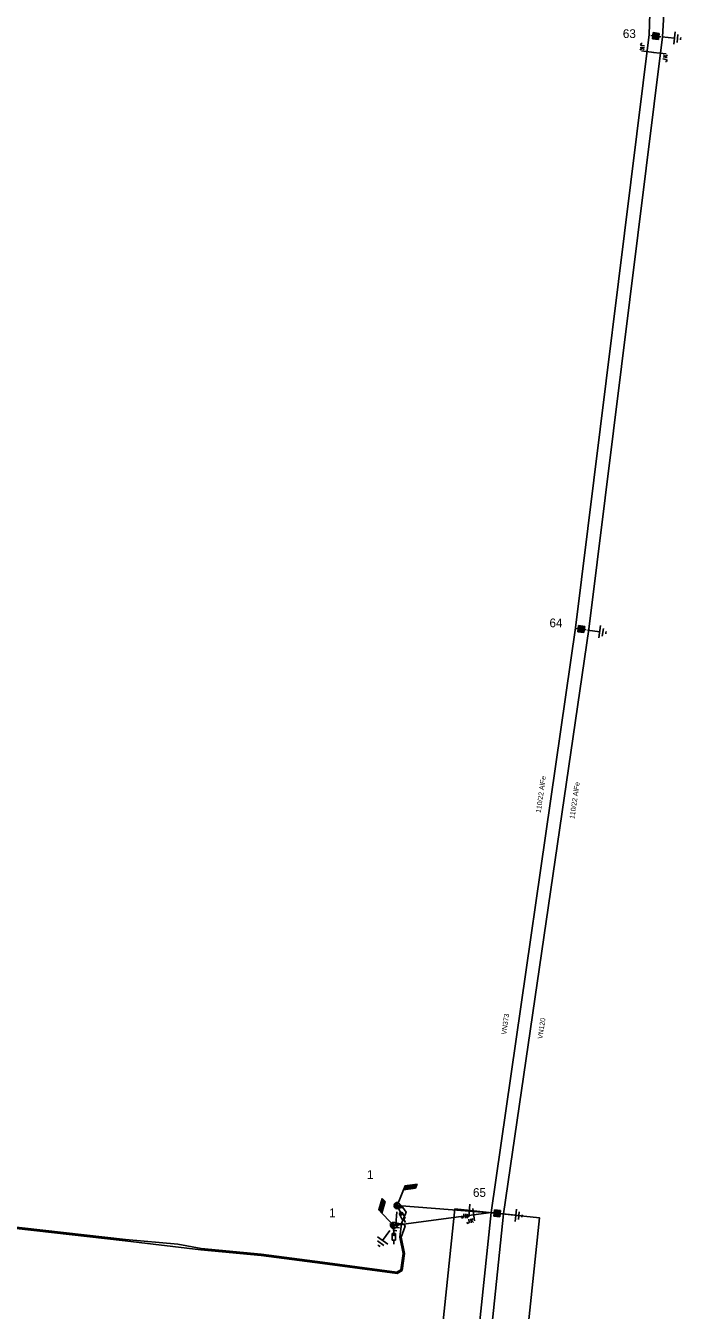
# Model space of a CAD drawing. Extents: x -540340 to -537226, y -1183949 to -1180375.
# Drawn here: x -540138.8 to -540007.7, y -1183666.6 to -1183409.6 of the extents above; entities that cross this region are included whole.
import ezdxf

# ---------------------------------------------------------------- set-up
doc = ezdxf.new("R2010")
doc.units = 0
for name, color, linetype in [('Default', 7, 'Continuous'), ('Vrstva 1', 7, 'Continuous'), ('Vrstva 11', 7, 'Continuous'), ('Vrstva 12', 7, 'Continuous'), ('Vrstva 13', 7, 'Continuous'), ('Vrstva 14', 7, 'Continuous'), ('Vrstva 15', 7, 'Continuous'), ('Vrstva 16', 7, 'Continuous'), ('Vrstva 18', 7, 'Continuous'), ('Vrstva 19', 7, 'Continuous'), ('Vrstva 2', 7, 'Continuous'), ('Vrstva 3', 7, 'Continuous'), ('Vrstva 35', 7, 'Continuous'), ('Vrstva 4', 7, 'Continuous'), ('Vrstva 5', 7, 'Continuous'), ('Vrstva 52', 7, 'Continuous')]:
    doc.layers.add(name, color=color, linetype=linetype)

# ---------------------------------------------------------------- blocks, each defined once
blk = doc.blocks.new('VN840')
at = {"layer": 'Vrstva 15'}
for points in [[(-0.01, 1.41), (-0.01, -1.09)], [(-1.51, -1.24), (-1.51, -1.15)], [(-1.48, -1.35), (-1.51, -1.24)], [(-1.33, -1.42), (-1.48, -1.35)], [(-1.27, -1.42), (-1.33, -1.42)], [(-1.13, -1.35), (-1.27, -1.42)], [(-1.09, -1.24), (-1.13, -1.35)], [(-1.09, -0.59), (-1.09, -1.24)], [(-0.68, -0.59), (-0.68, -1.42)], [(-0.68, -1.11), (-0.27, -0.59)], [(-0.54, -0.94), (-0.2, -1.42)]]:
    blk.add_lwpolyline(points, dxfattribs=at)
blk = doc.blocks.new('VN440')
at = {"layer": 'Vrstva 2'}
for points in [[(1.22, 0), (1.21, 0.13), (1.19, 0.25), (1.16, 0.38), (1.11, 0.5), (1.05, 0.61), (0.98, 0.72), (0.9, 0.82), (0.81, 0.91), (0.71, 0.99), (0.6, 1.06), (0.49, 1.12), (0.37, 1.16), (0.25, 1.2), (0.12, 1.22), (-0.01, 1.22), (-0.14, 1.22), (-0.26, 1.2), (-0.39, 1.16), (-0.51, 1.12), (-0.62, 1.06), (-0.73, 0.99), (-0.83, 0.91), (-0.92, 0.82), (-1, 0.72), (-1.07, 0.61), (-1.13, 0.5), (-1.18, 0.38), (-1.21, 0.25), (-1.23, 0.13), (-1.24, 0), (-1.23, -0.13), (-1.21, -0.26), (-1.18, -0.38), (-1.13, -0.5), (-1.07, -0.62), (-1, -0.73), (-0.92, -0.83), (-0.83, -0.92), (-0.73, -1), (-0.62, -1.07), (-0.51, -1.13), (-0.39, -1.17), (-0.26, -1.2), (-0.14, -1.23), (-0.01, -1.23), (0.12, -1.23), (0.25, -1.2), (0.37, -1.17), (0.49, -1.13), (0.6, -1.07), (0.71, -1), (0.81, -0.92), (0.9, -0.83), (0.98, -0.73), (1.05, -0.62), (1.11, -0.5), (1.16, -0.38), (1.19, -0.26), (1.21, -0.13), (1.22, 0)], [(-1.24, 0), (1.22, 0)], [(-1.18, -0.34), (1.1, -0.34)], [(-1.01, -0.63), (0.97, -0.63)], [(-0.74, -0.92), (0.68, -0.92)]]:
    blk.add_lwpolyline(points, dxfattribs=at)
blk = doc.blocks.new('VN890')
at = {"layer": 'Vrstva 4'}
for points in [[(-0.41, 0.41), (0.41, 0)], [(-0.41, -0.41), (-0.41, 0.41)], [(0.41, 0), (-0.41, -0.41)], [(-0.34, 0.31), (0.27, 0), (-0.34, -0.3), (-0.34, 0.31)], [(-0.26, 0.2), (0.1, 0), (-0.26, -0.18), (-0.26, 0.2)], [(-0.19, 0.09), (-0.04, 0), (-0.19, -0.08), (-0.19, 0.09)], [(-0.16, -0.01), (-0.16, 0.03), (-0.13, 0.01), (-0.16, -0.01)]]:
    blk.add_lwpolyline(points, dxfattribs=at)
blk = doc.blocks.new('VN820')
at = {"layer": 'Vrstva 13'}
for points in [[(0, 0), (0, -2.1)], [(-0.32, -1.63), (0.34, -1.63)], [(-0.32, -2.95), (-0.32, -1.63)], [(0, -2.1), (-0.12, -1.86)], [(0, -2.1), (0.12, -1.86)], [(0.34, -1.63), (0.34, -2.95)], [(0.34, -2.95), (-0.32, -2.95)], [(0, -2.95), (0, -3.75)]]:
    blk.add_lwpolyline(points, dxfattribs=at)
blk = doc.blocks.new('VN810')
at = {"layer": 'Vrstva 14'}
for points in [[(0, -1.25), (0, -3.75)], [(1.25, -3.75), (-1.25, -3.75)], [(0.77, -4.37), (-0.8, -4.37)], [(0, -5), (-0.25, -5)], [(0.27, -5), (0, -5)]]:
    blk.add_lwpolyline(points, dxfattribs=at)
blk = doc.blocks.new('VN001')
at = {"layer": 'Default'}
for p, q in [((1.73, 3.03), (4.14, 3.03)), ((1.76, 3.08), (4.17, 3.08)), ((1.79, 3.13), (4.2, 3.13)), ((1.82, 3.18), (4.23, 3.18)), ((1.85, 3.23), (4.26, 3.23)), ((1.87, 3.28), (4.29, 3.28)), ((1.9, 3.33), (4.32, 3.33)), ((1.93, 3.38), (4.35, 3.38)), ((1.96, 3.43), (4.37, 3.43)), ((1.99, 3.48), (4.4, 3.48)), ((2.02, 3.53), (4.43, 3.53)), ((2.05, 3.58), (4.46, 3.58)), ((2.07, 3.63), (4.49, 3.63)), ((2.1, 3.68), (4.52, 3.68)), ((2.13, 3.73), (2.54, 3.73))]:
    blk.add_line(p, q, dxfattribs=at)
blk.add_lwpolyline([(2.13, 3.73), (0, 0)], dxfattribs=at)
blk.add_lwpolyline([(4.55, 3.73), (2.13, 3.73), (1.7, 2.98), (4.12, 2.99)], close=True, dxfattribs=at)
blk = doc.blocks.new('VN470')
at = {"layer": 'Vrstva 2'}
for points in [[(-1.23, 1.22), (1.23, 1.22)], [(-1.23, -1.23), (-1.23, 1.22)], [(-0.92, 0.9), (0.92, 0.9)], [(-0.92, -0.95), (-0.92, 0.9)], [(-0.61, 0.61), (0.61, 0.61)], [(-0.61, -0.62), (-0.61, 0.61)], [(-0.31, -0.27), (-0.31, 0.34)], [(-0.31, 0.34), (0.31, 0.34)], [(0, 1.22), (0, 1.97)], [(0.31, 0.34), (0.31, -0.27)], [(0.61, 0.61), (0.61, -0.62)], [(0.92, 0.9), (0.92, -0.95)], [(1.23, 1.22), (1.23, -1.23)], [(1.23, -1.23), (-1.23, -1.23)], [(0.92, -0.95), (-0.92, -0.95)], [(0.61, -0.62), (-0.61, -0.62)], [(0.31, -0.27), (-0.31, -0.27)], [(0, -1.23), (0, -1.98)]]:
    blk.add_lwpolyline(points, dxfattribs=at)

msp = doc.modelspace()

# ---------------------------------------------------------------- linework, layer by layer
at = {"layer": 'Vrstva 1'}
for points in [[(-540012.36, -1183354.43), (-540014.17, -1183411.34), (-540028.85, -1183530.04), (-540045.72, -1183647.03)], [(-540008.15, -1183354.48), (-540011.44, -1183411.77), (-540026.2, -1183530.3), (-540043.23, -1183647.3)], [(-540045.72, -1183647.03), (-540058.25, -1183766.71), (-540064.83, -1183821.78)], [(-540043.23, -1183647.3), (-540055.69, -1183767.11), (-540062.23, -1183822.93)]]:
    msp.add_lwpolyline(points, dxfattribs=at)
at = {"layer": 'Vrstva 35'}
msp.add_lwpolyline([(-540099.18, -1183843.5), (-540075.2, -1183846.48), (-540065.47, -1183765.95), (-540052.99, -1183646.29), (-540036.08, -1183648.06), (-540048.58, -1183767.85), (-540059.33, -1183856.85), (-540059.45, -1183876.18), (-540076.45, -1183876.06), (-540087.82, -1183869.73), (-540106.08, -1183859.73), (-540163.52, -1183816.9), (-540239.44, -1183760.31), (-540323.17, -1183697.88), (-540340.03, -1183685.32), (-540338.32, -1183665.38), (-540313.01, -1183684.25), (-540229.28, -1183746.68), (-540153.36, -1183803.27)], close=True, dxfattribs=at)
at = {"layer": 'Vrstva 5'}
for points in [[(-540064.54, -1183645.65), (-540063.36, -1183646.02), (-540062.73, -1183646.93), (-540063.66, -1183649.2), (-540064.01, -1183651.97), (-540063.31, -1183655.22), (-540063.78, -1183658.46), (-540064.6, -1183658.99), (-540079.45, -1183656.99), (-540091.69, -1183655.36), (-540103.73, -1183654.24), (-540108.4, -1183653.33), (-540118.87, -1183652.43), (-540155.48, -1183648.29)], [(-540065.23, -1183649.61), (-540063.66, -1183649.2), (-540063.19, -1183649.36), (-540062.91, -1183649.73), (-540063.75, -1183651.96), (-540063.06, -1183655.22), (-540063.55, -1183658.61), (-540064.54, -1183659.25), (-540079.48, -1183657.24), (-540091.72, -1183655.61), (-540103.75, -1183654.49), (-540118.9, -1183652.68), (-540155.51, -1183648.54)]]:
    msp.add_lwpolyline(points, dxfattribs=at)
at = {"layer": 'Vrstva 52'}
for points in [[(-540043.23, -1183647.3), (-540064.54, -1183645.65)], [(-540045.72, -1183647.03), (-540065.23, -1183649.61)]]:
    msp.add_lwpolyline(points, dxfattribs=at)

# ---------------------------------------------------------------- block references
at = {"layer": 'Vrstva 11'}
for p, rotation in [((-540064.54, -1183645.65), 7.688058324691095), ((-540065.23, -1183649.61), 73.67263312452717)]:
    msp.add_blockref('VN001', p, dxfattribs=dict(at, rotation=rotation))
at = {"layer": 'Vrstva 13'}
for name, p, xscale, yscale, rotation in [('VN470', (-540012.82, -1183411.65), 0.49999999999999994, 0.49999999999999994, 82.98433892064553), ('VN470', (-540027.73, -1183530.3), 0.5, 0.5, 81.76570554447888), ('VN440', (-540064.54, -1183645.65), 0.5, 0.49999999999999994, -93.51351665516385), ('VN470', (-540044.54, -1183647.18), 0.5, 0.5, 84.0429694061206), ('VN440', (-540065.23, -1183649.61), 0.5, 0.5, -70.16778056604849)]:
    msp.add_blockref(name, p, dxfattribs=dict(at, xscale=xscale, yscale=yscale, rotation=rotation))
at = {"layer": 'Vrstva 15'}
for p, rotation in [((-540012.82, -1183411.65), 83.96296944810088), ((-540027.73, -1183530.3), 81.76570561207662), ((-540044.54, -1183647.18), 83.75617783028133), ((-540064.54, -1183645.65), -3.34249164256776), ((-540065.23, -1183649.61), -35.94625827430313)]:
    msp.add_blockref('VN810', p, dxfattribs=dict(at, rotation=rotation))
at = {"layer": 'Vrstva 16'}
for p, rotation in [((-540064.54, -1183645.65), 26.129327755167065), ((-540065.23, -1183649.61), 0.2898526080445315)]:
    msp.add_blockref('VN820', p, dxfattribs=dict(at, rotation=rotation))
at = {"layer": 'Vrstva 18'}
for p, rotation in [((-540014.59, -1183414.77), -97.0508000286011), ((-540011.85, -1183415.08), 82.90211393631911), ((-540050.07, -1183646.77), -4.4259028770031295), ((-540049.21, -1183647.62), 7.076163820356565)]:
    msp.add_blockref('VN840', p, dxfattribs=dict(at, rotation=rotation))
at = {"layer": 'Vrstva 19'}
for p, rotation in [((-540063.75, -1183645.9), -17.378925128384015), ((-540064.31, -1183649.37), 14.628316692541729)]:
    msp.add_blockref('VN890', p, dxfattribs=dict(at, rotation=rotation))

# ---------------------------------------------------------------- texts
at = {"layer": 'Vrstva 12'}
for p in [(-540070.57, -1183640.31), (-540078.14, -1183647.97)]:
    msp.add_text('1', height=1.75, dxfattribs=at).set_placement(p)
at = {"layer": 'Vrstva 14'}
for s, p in [('63', (-540019.4, -1183412.04)), ('64', (-540034.07, -1183529.93)), ('65', (-540049.37, -1183643.9))]:
    msp.add_text(s, height=1.75, dxfattribs=at).set_placement(p)
at = {"layer": 'Vrstva 2'}
for rotation, p in [(81.792, (-540035.82, -1183567.13)), (81.718, (-540029.09, -1183568.34))]:
    msp.add_text('110/22 AlFe', height=1, rotation=rotation, dxfattribs=at).set_placement(p)
at = {"layer": 'Vrstva 3'}
for s, rotation, p in [('VN373', 81.792, (-540042.72, -1183611.49)), ('VN120', 81.718, (-540035.48, -1183612.35))]:
    msp.add_text(s, height=1, rotation=rotation, dxfattribs=at).set_placement(p)

doc.saveas('drawing.dxf')
